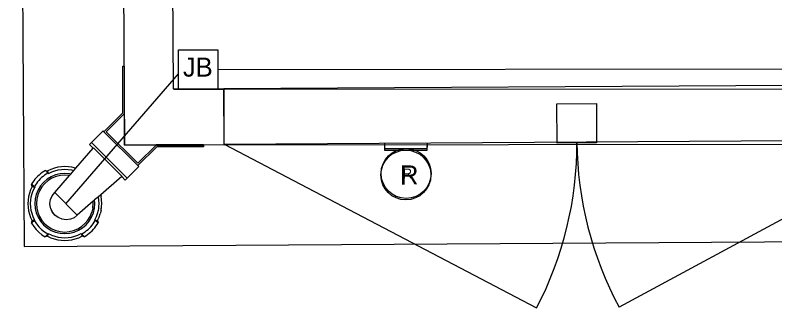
# Model space of a CAD drawing. Extents: x -2.6 to 16.3, y -2.7 to 7.5.
# Drawn here: x -0.045 to 3.723, y -0.304 to 1.148 of the extents above; entities that cross this region are included whole.
import ezdxf

# ---------------------------------------------------------------- set-up
doc = ezdxf.new("R2010")
doc.units = 0
for name, color, linetype in [('Default', 7, 'Continuous'), ('HS_Concrete_Object', 7, 'Continuous'), ('HS_Dimensions_and_Text', 7, 'Continuous'), ('HS_Electrical_Devices', 7, 'Continuous'), ('HS_Miscellaneous', 7, 'Continuous')]:
    doc.layers.add(name, color=color, linetype=linetype)

msp = doc.modelspace()

# ---------------------------------------------------------------- linework, layer by layer
at = {"layer": 'Default'}
for p, q in [((0.4888, 0.8952), (0.497, 0.8952)), ((0.8894, 0.5057), (0.6539, 0.5042)), ((0.8894, 0.4975), (0.6574, 0.496)), ((0.8894, 0.5057), (0.8894, 0.4975)), ((0.0192, 0.2307), (0.0183, 0.213)), ((0.0183, 0.213), (0.0192, 0.1954)), ((0.1491, 0.0379), (0.1662, 0.0337)), ((0.2364, 0.034), (0.2536, 0.0382)), ((0.1662, 0.0337), (0.1837, 0.0312)), ((0.1837, 0.0312), (0.2013, 0.0304)), ((0.2013, 0.0304), (0.219, 0.0313)), ((0.219, 0.0313), (0.2364, 0.034))]:
    msp.add_line(p, q, dxfattribs=at)
at = {"layer": 'HS_Concrete_Object'}
for p, q in [((0.9899, 0.7839), (4.4898, 0.8062)), ((0.9916, 0.5063), (0.9899, 0.7839)), ((0.9916, 0.5084), (4.4915, 0.5316)), ((4.4915, 0.5307), (2.9519, -0.3012)), ((0.9916, 0.5084), (2.5417, -0.3038)), ((1.7878, 0.5141), (1.788, 0.4861)), ((1.9985, 0.4875), (1.9998, 0.5154)), ((1.788, 0.4861), (1.9985, 0.4875))]:
    msp.add_line(p, q, dxfattribs=at)
for points in [[(15.9556, 7.1018), (-0.0446, 6.9998), (0, 0), (16.0002, 0.1019)], [(2.6428, 0.7089), (2.8381, 0.7102), (2.8393, 0.5149), (2.644, 0.5136)]]:
    msp.add_lwpolyline(points, close=True, dxfattribs=at)
for points in [[(15.4629, 5.9473), (15.4588, 6.5986), (0.4591, 6.5025), (0.4974, 0.5032), (0.9916, 0.5063)], [(0.7399, 0.7823), (0.7054, 6.1941), (15.1483, 6.2872)], [(0.7399, 0.7823), (0.9899, 0.7839)]]:
    msp.add_lwpolyline(points, dxfattribs=at)
msp.add_circle((1.8941, 0.363), 0.1238, dxfattribs=at)
for centre, start, end in [((0.9916, 0.5084), 332.3453, 0.3403), ((4.4915, 0.5307), 180.3898, 208.3848)]:
    msp.add_arc(centre, 1.75, start, end, dxfattribs=at)
at = {"layer": 'HS_Electrical_Devices'}
for p, q in [((0.489, 0.6632), (0.4888, 0.8952)), ((0.4972, 0.6598), (0.497, 0.8952)), ((0.9601, 0.8788), (5.3352, 0.8828)), ((0.2072, 0.2122), (0.7648, 0.8579)), ((0.9914, 0.7811), (4.4914, 0.7843)), ((0.9917, 0.5036), (0.9914, 0.7812)), ((0.3958, 0.5698), (0.489, 0.6632)), ((0.4972, 0.6598), (0.4074, 0.5698)), ((0.4974, 0.5032), (0.4972, 0.6598)), ((0.3335, 0.516), (0.3915, 0.5741)), ((0.3915, 0.5741), (0.3958, 0.5698)), ((0.3958, 0.5698), (0.5642, 0.4017)), ((0.4074, 0.5698), (0.5642, 0.4133)), ((0.3243, 0.5067), (0.3335, 0.516)), ((0.3243, 0.5067), (0.3418, 0.4892)), ((0.5105, 0.3394), (0.3335, 0.516)), ((0.3418, 0.4892), (0.3431, 0.4907)), ((0.4851, 0.3489), (0.3431, 0.4907)), ((0.654, 0.5033), (0.4974, 0.5032)), ((0.5642, 0.4133), (0.654, 0.5033)), ((0.6574, 0.4951), (0.5642, 0.4017)), ((0.8894, 0.5035), (0.654, 0.5033)), ((0.8894, 0.4953), (0.6574, 0.4951)), ((0.8894, 0.5035), (0.8894, 0.4953)), ((0.9917, 0.5057), (4.4917, 0.5098)), ((1.7879, 0.507), (1.7879, 0.479)), ((1.9985, 0.4792), (1.9999, 0.5071)), ((0.2557, 0.3891), (0.3418, 0.4892)), ((1.7879, 0.479), (1.9985, 0.4792)), ((0.1051, 0.3784), (0.0968, 0.3732)), ((0.1051, 0.3784), (0.1076, 0.3756)), ((0.1051, 0.3784), (0.117, 0.3758)), ((0.133, 0.3833), (0.117, 0.3758)), ((0.1497, 0.3892), (0.133, 0.3833)), ((0.1669, 0.3935), (0.1497, 0.3892)), ((0.1522, 0.3761), (0.1685, 0.3803)), ((0.1843, 0.3961), (0.1669, 0.3935)), ((0.1685, 0.3803), (0.1852, 0.3828)), ((0.202, 0.397), (0.1843, 0.3961)), ((0.1852, 0.3828), (0.2019, 0.3837)), ((0.2019, 0.3837), (0.2187, 0.3829)), ((0.2196, 0.3962), (0.202, 0.397)), ((0.2187, 0.3829), (0.2353, 0.3805)), ((0.2371, 0.3937), (0.2196, 0.3962)), ((0.2306, 0.3598), (0.246, 0.3778)), ((0.2353, 0.3805), (0.246, 0.3778)), ((0.2542, 0.3896), (0.2371, 0.3937)), ((0.246, 0.3778), (0.2557, 0.3891)), ((0.2557, 0.3891), (0.2542, 0.3896)), ((0.5685, 0.3974), (0.5105, 0.3394)), ((0.5642, 0.4017), (0.5685, 0.3974)), ((0.0599, 0.3414), (0.0535, 0.334)), ((0.0666, 0.3485), (0.0599, 0.3414)), ((0.0737, 0.3552), (0.0666, 0.3485)), ((0.0811, 0.3616), (0.0737, 0.3552)), ((0.0864, 0.3421), (0.0795, 0.3356)), ((0.0888, 0.3676), (0.0811, 0.3616)), ((0.0937, 0.3483), (0.0864, 0.3421)), ((0.0968, 0.3732), (0.0888, 0.3676)), ((0.1013, 0.3541), (0.0937, 0.3483)), ((0.1092, 0.3594), (0.1013, 0.3541)), ((0.1076, 0.3756), (0.1101, 0.3728)), ((0.1173, 0.3643), (0.1092, 0.3594)), ((0.1101, 0.3728), (0.1125, 0.37)), ((0.1125, 0.37), (0.115, 0.3672)), ((0.1342, 0.3464), (0.1142, 0.3341)), ((0.115, 0.3672), (0.1173, 0.3643)), ((0.1213, 0.363), (0.117, 0.3758)), ((0.1213, 0.363), (0.1173, 0.3643)), ((0.1377, 0.3394), (0.1188, 0.3277)), ((0.1213, 0.363), (0.1364, 0.3703)), ((0.1558, 0.3554), (0.1342, 0.3464)), ((0.1364, 0.3703), (0.1522, 0.3761)), ((0.1582, 0.3479), (0.1377, 0.3394)), ((0.1514, 0.2679), (0.2248, 0.3532)), ((0.1786, 0.3609), (0.1558, 0.3554)), ((0.1798, 0.3532), (0.1582, 0.3479)), ((0.2019, 0.3629), (0.1786, 0.3609)), ((0.2019, 0.355), (0.1798, 0.3532)), ((0.2252, 0.3611), (0.2019, 0.3629)), ((0.224, 0.3533), (0.2019, 0.355)), ((0.2248, 0.3532), (0.224, 0.3533)), ((0.2248, 0.3532), (0.2306, 0.3598)), ((0.2306, 0.3598), (0.2252, 0.3611)), ((0.4837, 0.3476), (0.3796, 0.2575)), ((0.4851, 0.3489), (0.4837, 0.3476)), ((0.4837, 0.3476), (0.5012, 0.3301)), ((0.5012, 0.3301), (0.5105, 0.3394)), ((0.042, 0.3182), (0.0368, 0.3099)), ((0.0396, 0.3074), (0.0368, 0.3099)), ((0.0394, 0.2981), (0.0368, 0.3099)), ((0.0424, 0.305), (0.0396, 0.3074)), ((0.0475, 0.3262), (0.042, 0.3182)), ((0.0452, 0.3025), (0.0424, 0.305)), ((0.048, 0.3001), (0.0452, 0.3025)), ((0.0535, 0.334), (0.0475, 0.3262)), ((0.0558, 0.3059), (0.0509, 0.2977)), ((0.0611, 0.3138), (0.0558, 0.3059)), ((0.0668, 0.3214), (0.0611, 0.3138)), ((0.073, 0.3287), (0.0668, 0.3214)), ((0.0795, 0.3356), (0.073, 0.3287)), ((0.0964, 0.3188), (0.0811, 0.3009)), ((0.1019, 0.3133), (0.0875, 0.2963)), ((0.1142, 0.3341), (0.0964, 0.3188)), ((0.1188, 0.3277), (0.1019, 0.3133)), ((0.0261, 0.2653), (0.0218, 0.2482)), ((0.0319, 0.282), (0.0261, 0.2653)), ((0.0394, 0.2981), (0.0319, 0.282)), ((0.0392, 0.2628), (0.0449, 0.2786)), ((0.0522, 0.2938), (0.0394, 0.2981)), ((0.0449, 0.2786), (0.0522, 0.2938)), ((0.0509, 0.2977), (0.048, 0.3001)), ((0.0509, 0.2977), (0.0522, 0.2938)), ((0.0689, 0.2809), (0.0599, 0.2593)), ((0.0759, 0.2774), (0.0673, 0.2569)), ((0.0811, 0.3009), (0.0689, 0.2809)), ((0.0875, 0.2963), (0.0759, 0.2774)), ((0.1385, 0.2526), (0.1514, 0.2679)), ((0.1514, 0.2679), (0.263, 0.1565)), ((0.0218, 0.2482), (0.0192, 0.2307)), ((0.0317, 0.2131), (0.0325, 0.2299)), ((0.0325, 0.2299), (0.0351, 0.2465)), ((0.0351, 0.2465), (0.0392, 0.2628)), ((0.0544, 0.2365), (0.0525, 0.2132)), ((0.0599, 0.2593), (0.0544, 0.2365)), ((0.0621, 0.2353), (0.0603, 0.2132)), ((0.0673, 0.2569), (0.0621, 0.2353)), ((0.1276, 0.2138), (0.1303, 0.2341)), ((0.1303, 0.2341), (0.1385, 0.2526)), ((0.3495, 0.2314), (0.3421, 0.225)), ((0.3684, 0.2477), (0.3495, 0.2314)), ((0.3508, 0.2143), (0.3495, 0.2314)), ((0.3796, 0.2575), (0.3684, 0.2477)), ((0.3684, 0.2477), (0.3684, 0.2478)), ((0.3708, 0.2311), (0.3684, 0.2477)), ((0.3716, 0.2143), (0.3708, 0.2311)), ((0.3796, 0.2575), (0.3816, 0.2495)), ((0.3841, 0.232), (0.3816, 0.2495)), ((0.3849, 0.2144), (0.3841, 0.232)), ((0.0192, 0.1954), (0.0217, 0.1779)), ((0.0325, 0.1963), (0.0317, 0.2131)), ((0.0349, 0.1797), (0.0325, 0.1963)), ((0.0525, 0.2132), (0.0543, 0.1898)), ((0.0543, 0.1898), (0.0597, 0.1671)), ((0.0603, 0.2132), (0.062, 0.1911)), ((0.062, 0.1911), (0.0672, 0.1696)), ((0.1305, 0.1931), (0.1276, 0.2138)), ((0.1321, 0.1892), (0.1305, 0.1931)), ((0.139, 0.1727), (0.1321, 0.1892)), ((0.1388, 0.1736), (0.1321, 0.1892)), ((0.3421, 0.225), (0.263, 0.1565)), ((0.3412, 0.1921), (0.3359, 0.1705)), ((0.3412, 0.1921), (0.3429, 0.2142)), ((0.3429, 0.2142), (0.3421, 0.225)), ((0.3434, 0.1681), (0.3489, 0.1909)), ((0.3489, 0.1909), (0.3508, 0.2143)), ((0.3695, 0.1877), (0.3708, 0.1975)), ((0.3708, 0.1975), (0.3716, 0.2143)), ((0.3815, 0.1793), (0.384, 0.1967)), ((0.3826, 0.1857), (0.384, 0.1967)), ((0.384, 0.1967), (0.3849, 0.2144)), ((0.0217, 0.1779), (0.0259, 0.1608)), ((0.0259, 0.1608), (0.0317, 0.1442)), ((0.039, 0.1634), (0.0349, 0.1797)), ((0.0447, 0.1477), (0.039, 0.1634)), ((0.0597, 0.1671), (0.0686, 0.1455)), ((0.0672, 0.1696), (0.0756, 0.1491)), ((0.1519, 0.1567), (0.1388, 0.1736)), ((0.1515, 0.1564), (0.139, 0.1727)), ((0.1679, 0.1439), (0.1515, 0.1564)), ((0.1523, 0.1564), (0.1519, 0.1567)), ((0.1688, 0.1437), (0.1523, 0.1564)), ((0.263, 0.1565), (0.2477, 0.1435)), ((0.3274, 0.15), (0.3359, 0.1705)), ((0.3344, 0.1465), (0.3434, 0.1681)), ((0.3584, 0.1488), (0.3641, 0.1646)), ((0.3641, 0.1646), (0.3682, 0.1809)), ((0.3682, 0.1809), (0.3695, 0.1877)), ((0.3714, 0.1454), (0.3772, 0.1621)), ((0.3815, 0.1793), (0.3772, 0.1621)), ((0.3815, 0.1793), (0.3826, 0.1857)), ((0.0317, 0.1442), (0.0391, 0.1282)), ((0.0365, 0.1163), (0.0391, 0.1282)), ((0.0365, 0.1163), (0.0392, 0.1188)), ((0.0365, 0.1163), (0.0471, 0.1001)), ((0.0519, 0.1325), (0.0391, 0.1282)), ((0.0392, 0.1188), (0.042, 0.1213)), ((0.042, 0.1213), (0.0449, 0.1238)), ((0.0519, 0.1325), (0.0447, 0.1477)), ((0.0449, 0.1238), (0.0477, 0.1262)), ((0.0477, 0.1262), (0.0506, 0.1286)), ((0.0516, 0.1317), (0.0506, 0.1286)), ((0.0506, 0.1286), (0.0607, 0.1126)), ((0.0516, 0.1317), (0.0519, 0.1325)), ((0.0686, 0.1455), (0.0808, 0.1256)), ((0.0756, 0.1491), (0.0872, 0.1302)), ((0.0808, 0.1256), (0.096, 0.1079)), ((0.0872, 0.1302), (0.1016, 0.1134)), ((0.1016, 0.1134), (0.1184, 0.0991)), ((0.1844, 0.1371), (0.1679, 0.1439)), ((0.1844, 0.1371), (0.1688, 0.1437)), ((0.1883, 0.1354), (0.1844, 0.1371)), ((0.2089, 0.1326), (0.1883, 0.1354)), ((0.2293, 0.1354), (0.2089, 0.1326)), ((0.2477, 0.1435), (0.2293, 0.1354)), ((0.2845, 0.0997), (0.3014, 0.1142)), ((0.3014, 0.1142), (0.3158, 0.1311)), ((0.3069, 0.1086), (0.3221, 0.1265)), ((0.3158, 0.1311), (0.3274, 0.15)), ((0.3221, 0.1265), (0.3344, 0.1465)), ((0.3364, 0.106), (0.3422, 0.1136)), ((0.3422, 0.1136), (0.3475, 0.1215)), ((0.3475, 0.1215), (0.3524, 0.1297)), ((0.3511, 0.1336), (0.3584, 0.1488)), ((0.3511, 0.1336), (0.3639, 0.1293)), ((0.3524, 0.1297), (0.3511, 0.1336)), ((0.3524, 0.1297), (0.3553, 0.1273)), ((0.3553, 0.1273), (0.3581, 0.1249)), ((0.3581, 0.1249), (0.3609, 0.1224)), ((0.3609, 0.1224), (0.3637, 0.12)), ((0.3613, 0.1092), (0.3665, 0.1175)), ((0.3637, 0.12), (0.3665, 0.1175)), ((0.3639, 0.1293), (0.3714, 0.1454)), ((0.3639, 0.1293), (0.3665, 0.1175)), ((0.0471, 0.1001), (0.0594, 0.085)), ((0.0594, 0.085), (0.0732, 0.0713)), ((0.0607, 0.1126), (0.0726, 0.0978)), ((0.0726, 0.0978), (0.086, 0.0844)), ((0.086, 0.0844), (0.1008, 0.0726)), ((0.096, 0.1079), (0.1138, 0.0927)), ((0.1138, 0.0927), (0.1337, 0.0806)), ((0.1184, 0.0991), (0.1373, 0.0876)), ((0.1337, 0.0806), (0.1553, 0.0717)), ((0.1373, 0.0876), (0.1577, 0.0792)), ((0.1577, 0.0792), (0.1793, 0.0741)), ((0.2235, 0.0742), (0.2451, 0.0795)), ((0.2451, 0.0795), (0.2656, 0.088)), ((0.2475, 0.072), (0.2691, 0.0811)), ((0.2656, 0.088), (0.2845, 0.0997)), ((0.2691, 0.0811), (0.2891, 0.0934)), ((0.2891, 0.0934), (0.3069, 0.1086)), ((0.302, 0.0733), (0.3096, 0.0791)), ((0.3096, 0.0791), (0.3168, 0.0853)), ((0.3168, 0.0853), (0.3237, 0.0918)), ((0.3237, 0.0918), (0.3303, 0.0988)), ((0.3296, 0.0722), (0.3367, 0.0789)), ((0.3303, 0.0988), (0.3364, 0.106)), ((0.3367, 0.0789), (0.3434, 0.086)), ((0.3434, 0.086), (0.3498, 0.0934)), ((0.3498, 0.0934), (0.3557, 0.1012)), ((0.3557, 0.1012), (0.3613, 0.1092)), ((0.0732, 0.0713), (0.0883, 0.059)), ((0.0883, 0.059), (0.1045, 0.0484)), ((0.1008, 0.0726), (0.1168, 0.0625)), ((0.107, 0.0511), (0.1045, 0.0484)), ((0.1164, 0.051), (0.1045, 0.0484)), ((0.1095, 0.0539), (0.107, 0.0511)), ((0.112, 0.0568), (0.1095, 0.0539)), ((0.1144, 0.0596), (0.112, 0.0568)), ((0.1168, 0.0625), (0.1144, 0.0596)), ((0.1164, 0.051), (0.1196, 0.0606)), ((0.1164, 0.051), (0.1324, 0.0436)), ((0.1168, 0.0625), (0.1199, 0.0635)), ((0.1199, 0.0635), (0.1196, 0.0606)), ((0.1359, 0.0566), (0.1199, 0.0635)), ((0.1324, 0.0436), (0.1491, 0.0379)), ((0.1359, 0.0566), (0.1517, 0.051)), ((0.1517, 0.051), (0.1679, 0.0469)), ((0.1553, 0.0717), (0.178, 0.0663)), ((0.1679, 0.0469), (0.1846, 0.0445)), ((0.178, 0.0663), (0.2014, 0.0646)), ((0.1793, 0.0741), (0.2014, 0.0724)), ((0.1846, 0.0445), (0.2013, 0.0437)), ((0.2013, 0.0437), (0.2181, 0.0446)), ((0.2014, 0.0724), (0.2235, 0.0742)), ((0.2014, 0.0646), (0.2247, 0.0665)), ((0.2181, 0.0446), (0.2347, 0.0472)), ((0.2247, 0.0665), (0.2475, 0.072)), ((0.2347, 0.0472), (0.251, 0.0513)), ((0.251, 0.0513), (0.2669, 0.0571)), ((0.2536, 0.0382), (0.2703, 0.0441)), ((0.2669, 0.0571), (0.282, 0.0644)), ((0.2703, 0.0441), (0.2863, 0.0516)), ((0.282, 0.0644), (0.2863, 0.0516)), ((0.282, 0.0644), (0.2859, 0.0631)), ((0.2859, 0.0631), (0.2941, 0.068)), ((0.2883, 0.0603), (0.2859, 0.0631)), ((0.2982, 0.0491), (0.2863, 0.0516)), ((0.2908, 0.0574), (0.2883, 0.0603)), ((0.2932, 0.0546), (0.2908, 0.0574)), ((0.2957, 0.0518), (0.2932, 0.0546)), ((0.2941, 0.068), (0.302, 0.0733)), ((0.2982, 0.0491), (0.2957, 0.0518)), ((0.2982, 0.0491), (0.3064, 0.0542)), ((0.3064, 0.0542), (0.3145, 0.0598)), ((0.3145, 0.0598), (0.3222, 0.0658)), ((0.3222, 0.0658), (0.3296, 0.0722))]:
    msp.add_line(p, q, dxfattribs=at)
msp.add_lwpolyline([(0.7414, 0.7809), (0.9914, 0.7811)], dxfattribs=at)
msp.add_circle((1.8933, 0.3553), 0.1238, dxfattribs=at)
at = {"layer": 'HS_Miscellaneous'}
msp.add_lwpolyline([(0.7647, 0.9763), (0.96, 0.9764), (0.9602, 0.7811), (0.7649, 0.7809)], close=True, dxfattribs=at)

# ---------------------------------------------------------------- texts
at = {"layer": 'HS_Concrete_Object'}
msp.add_text('R', height=0.0472, rotation=0.365, dxfattribs=at).set_placement((1.8786, 0.3393))
at = {"layer": 'HS_Dimensions_and_Text'}
msp.add_text('JB', height=0.09437, rotation=0.0523, dxfattribs=at).set_placement((0.7876, 0.8435))
at = {"layer": 'HS_Electrical_Devices'}
msp.add_text('R', height=0.0944, rotation=0.0523, dxfattribs=at).set_placement((1.8644, 0.3081))

doc.saveas('drawing.dxf')
